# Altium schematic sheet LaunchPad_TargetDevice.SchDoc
size 431 x 279 mm; Date: Not shown in title block; ApprovedBy: Not shown in title block; CheckedBy: Not shown in title block; Author: Not shown in title block; CompanyName: Not shown in title block; Engineer: Not shown in title block; Organization: Not shown in title block; Address1: Not shown in title block; Address2: Not shown in title block; Address3: Not shown in title block; Address4: Not shown in title block; DocumentNumber: 2; Revision: Use project parameter SCH_Rev; SheetNumber: 2; SheetTotal: 3; PageSetup: Record=PageOptions¦CenterHorizontal=True¦CenterVertical=True¦PrintScale=1.00¦XCorrection=1.00¦YCorrection=1.00¦PrintKind=0¦BorderSize=5000000¦LeftOffset=0¦BottomOffset=0¦Orientation=2¦PaperLength=1000¦PaperWidth=1000¦Scale=100¦PaperSource=15¦PrintQuality=600¦MediaType=1¦DitherType=10¦PaperKind=Letter¦PrintScaleMode=1
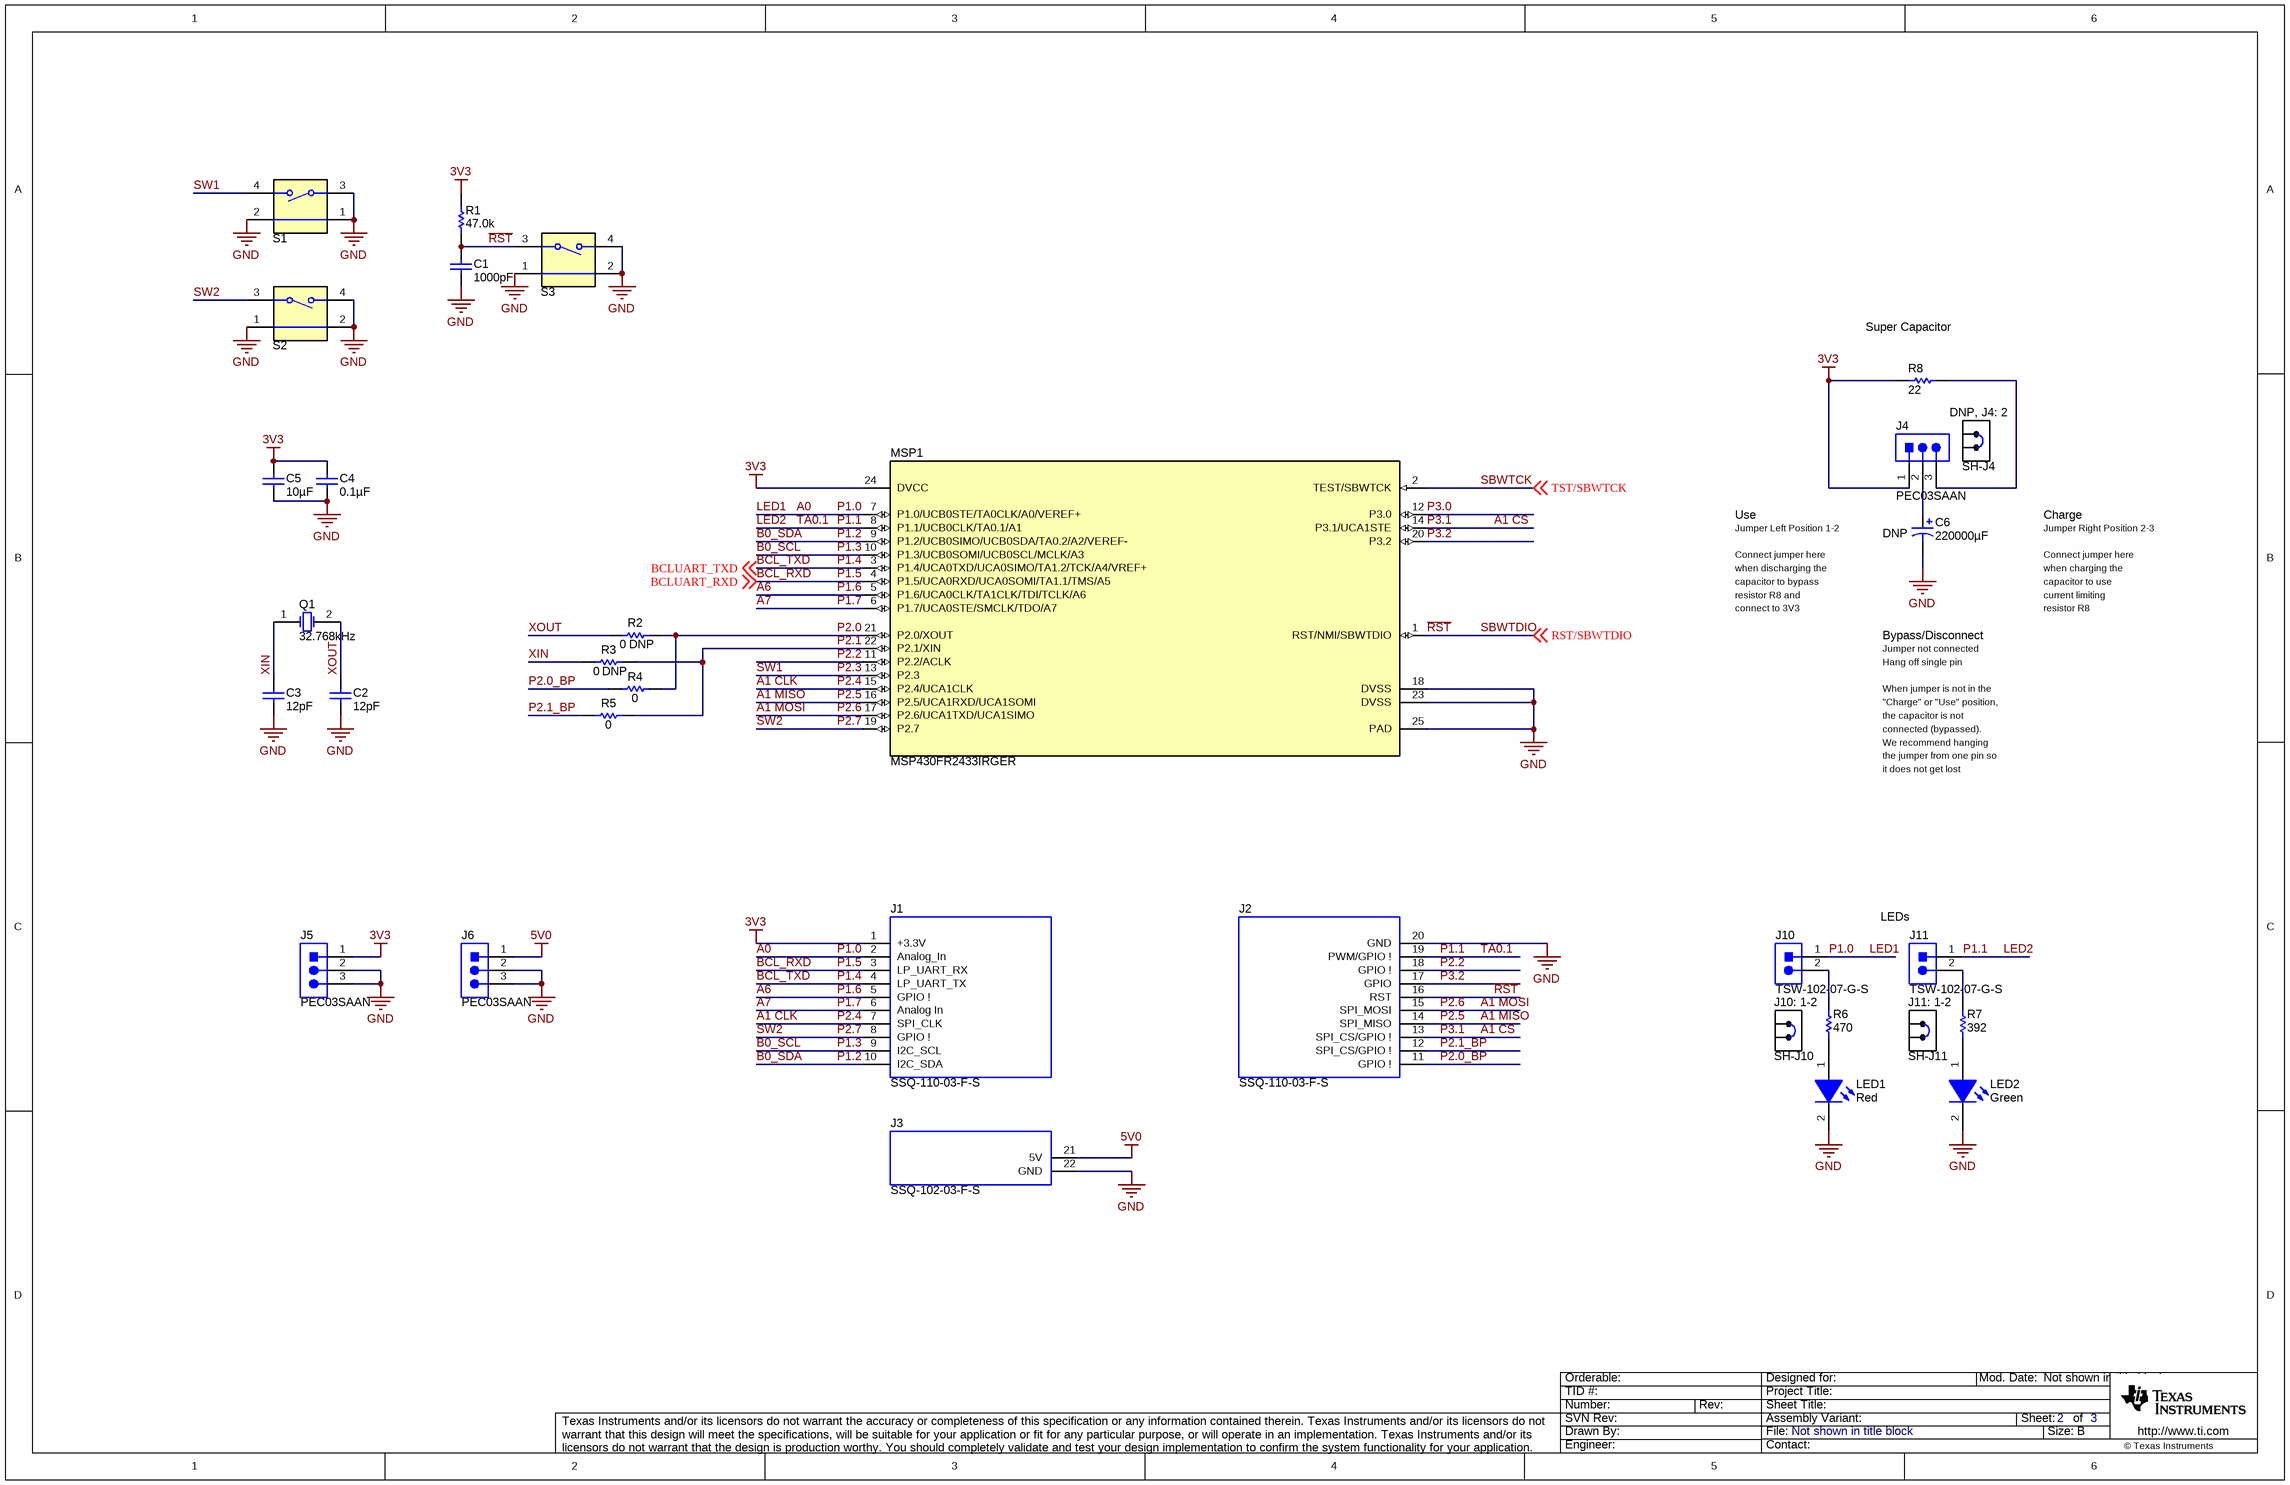
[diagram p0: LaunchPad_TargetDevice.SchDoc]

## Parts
C1  ValueDisplayed: 1000pF  [0402]  (hidden comment: GRM155R71H102KA01D)
C2  ValueDisplayed: 12pF  [0402]  (hidden comment: GRM1555C1E120JA01D)
C3  ValueDisplayed: 12pF  [0402]  (hidden comment: GRM1555C1E120JA01D)
C4  ValueDisplayed: 0.1µF  [0402]  (hidden comment: GRM155R61H104ME14D)
C5  ValueDisplayed: 10µF  [0603]  (hidden comment: GRM188R60J106ME84)
C6  ValueDisplayed: 220000µF  Note: DNP  [SD_1050x600]  (hidden comment: EEC-S0HD224H)
J1  SSQ-110-03-F-S  [BoosterPack_20pin_J1]
J2  SSQ-110-03-F-S  [BoosterPack_20pin_J2]
J3  SSQ-102-03-F-S  [BoosterPack_20pin_J3]
J4  PEC03SAAN  [CONN_PEC03SAAN]
J5  PEC03SAAN  [PEC03SAAN_Launchpad_3V3]
J6  PEC03SAAN  [PEC03SAAN_Launchpad_5V0]
J10  TSW-102-07-G-S  [TSW-102-07-G-S]
J11  TSW-102-07-G-S  [TSW-102-07-G-S]
LED1  value Red  [LED_LTST-C190_Red]  (hidden comment: LTST-C190CKT)
LED2  value Green  [LED_LTST-C190]  (hidden comment: LTST-C190GKT)
MSP1  MSP430FR2433IRGER  [RGE0024H]
Q1  Frequency: 32.768kHz  [Epson_FC-135]  (hidden comment: X1A0001410014)
R1  ValueDisplayed: 47.0k  [0402]  (hidden comment: RC0402FR-0747KL)
R2  ValueDisplayed: 0  Note: DNP  [0603]  (hidden comment: CRCW06030000Z0EA)
R3  ValueDisplayed: 0  Note: DNP  [0603]  (hidden comment: CRCW06030000Z0EA)
R4  ValueDisplayed: 0  [0603]  (hidden comment: CRCW06030000Z0EA)
R5  ValueDisplayed: 0  [0603]  (hidden comment: CRCW06030000Z0EA)
R6  ValueDisplayed: 470  [0402]  (hidden comment: RC0402FR-07470RL)
R7  ValueDisplayed: 392  [0402]  (hidden comment: CRCW0402392RFKED)
R8  ValueDisplayed: 22  [1206]  (hidden comment: CRCW120622R0JNEA)
S1  1188E-1K2-V-TR  [SW_1188E]  (value not drawn)
S2  1188E-1K2-V-TR  [SW_1188E]  (value not drawn)
S3  1188E-1K2-V-TR  [SW_1188E]  (value not drawn)
SH-J4  Note: DNP, J4: 2  [SNT-100-BK-G]  (hidden comment: SNT-100-BK-G)
SH-J10  Note: J10: 1-2  [SNT-100-BK-G]  (hidden comment: SNT-100-BK-G)
SH-J11  Note: J11: 1-2  [SNT-100-BK-G]  (hidden comment: SNT-100-BK-G)

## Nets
3V3: C4.1 C5.2 J1.1(+3.3V) J4.1 J5.1 MSP1.24(DVCC) R1.2 R8.1
5V0: J3.21(5V) J6.1
GND: C1.2 C2.2 C3.2 C4.2 C5.1 C6.2(-) J2.20(GND) J3.22(GND) J5.2 J5.3 J6.2 J6.3 LED1.2(K) LED2.2(K) MSP1.18(DVSS) MSP1.23(DVSS) MSP1.25(PAD) S1.1 S1.2 S1.3 S2.1 S2.2 S2.4 S3.1 S3.2 S3.4
A0: J1.2(Analog_In) J10.1 MSP1.7(P1.0/UCB0STE/TA0CLK/A0/VEREF+)  [also labelled LED1, P1.0]
A1 CLK: J1.7(SPI_CLK) MSP1.15(P2.4/UCA1CLK)  [also labelled P2.4]
A1 CS: J2.13(SPI_CS/GPIO_!) MSP1.14(P3.1/UCA1STE)  [also labelled P3.1]
A1 MISO: J2.14(SPI_MISO) MSP1.16(P2.5/UCA1RXD/UCA1SOMI)  [also labelled P2.5]
A1 MOSI: J2.15(SPI_MOSI) MSP1.17(P2.6/UCA1TXD/UCA1SIMO)  [also labelled P2.6]
A6: J1.5(GPIO_!) MSP1.5(P1.6/UCA0CLK/TA1CLK/TDI/TCLK/A6)  [also labelled P1.6]
A7: J1.6(Analog_In) MSP1.6(P1.7/UCA0STE/SMCLK/TDO/A7)  [also labelled P1.7]
B0_SCL: J1.9(I2C_SCL) MSP1.10(P1.3/UCB0SOMI/UCB0SCL/MCLK/A3)  [also labelled P1.3]
B0_SDA: J1.10(I2C_SDA) MSP1.9(P1.2/UCB0SIMO/UCB0SDA/TA0.2/A2/VEREF-)  [also labelled P1.2]
BCL_RXD: J1.3(LP_UART_RX) MSP1.4(P1.5/UCA0RXD/UCA0SOMI/TA1.1/TMS/A5) ; off-sheet BCLUART_RXD  [also labelled BCLUART_RXD, P1.5]
BCL_TXD: J1.4(LP_UART_TX) MSP1.3(P1.4/UCA0TXD/UCA0SIMO/TA1.2/TCK/A4/VREF+) ; off-sheet BCLUART_TXD  [also labelled BCLUART_TXD, P1.4]
LED2: J2.19(PWM/GPIO_!) J11.1 MSP1.8(P1.1/UCB0CLK/TA0.1/A1)  [also labelled P1.1, TA0.1]
P2.0: MSP1.21(P2.0/XOUT) R2.2 R4.2
P2.0_BP: J2.11(GPIO_!) R4.1
P2.1: MSP1.22(P2.1/XIN) R3.2 R5.2
P2.1_BP: J2.12(SPI_CS/GPIO_!) R5.1
P2.2: J2.18(GPIO_!) MSP1.11(P2.2/ACLK)
P2.3: MSP1.13(P2.3) S1.4  [also labelled SW1]
P2.7: J1.8(GPIO_!) MSP1.19(P2.7) S2.3  [also labelled SW2]
P3.0: MSP1.12(P3.0)
P3.2: J2.17(GPIO) MSP1.20(P3.2)
~{RST}: C1.1 J2.16(RST) MSP1.1(RST/NMI/SBWTDIO) R1.1 S3.3 ; off-sheet RST/SBWTDIO  [also labelled RST/SBWTDIO, SBWTDIO]
SBWTCK: MSP1.2(TEST/SBWTCK) ; off-sheet TST/SBWTCK  [also labelled TST/SBWTCK]
XIN: C3.1 Q1.1(OSC1) R3.1
XOUT: C2.1 Q1.2(OSC2) R2.1
NetC6_1: C6.1(+) J4.2
NetJ4_3: J4.3 R8.2
NetJ10_2: J10.2 R6.2
NetJ11_2: J11.2 R7.2
NetLED1_1: LED1.1(A) R6.1
NetLED2_1: LED2.1(A) R7.1

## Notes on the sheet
- (near R8) Super Capacitor
- Use
- Jumper Left Position 1-2
- Connect jumper here
- when discharging the
- Charge
- Jumper Right Position 2-3
- when charging the
- capacitor to bypass
- resistor R8 and
- connect to 3V3
- Bypass/Disconnect
- capacitor to use
- current limiting
- resistor R8
- Jumper not connected
- When jumper is not in the
- "Charge" or "Use" position,
- Hang off single pin
- the capacitor is not
- connected (bypassed).
- We recommend hanging
- the jumper from one pin so
- it does not get lost
- (near J11) LEDs

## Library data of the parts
C1 = GRM155R71H102KA01D: CAP, CERM, 1000 pF, 50 V, +/- 10%, X7R, 0402; Manufacturer: MuRata; Polarized: N; CompType: Capacitor; Value: 1000pF; U/M: EA; Cap_F: 0.000000001; Tolerance_%: 10; Value1: Unknown; VDC_V: 50; Value2: 50V; TaMin_C: -55; TaMax_C: 125; SizeArea_mm2: 0.5; SizeAreaWB_mm2: 3; SizeX_mm: 1; SizeZ_mm: 0.6; AEC Category: Q200
C2 C3 = GRM1555C1E120JA01D: CAP, CERM, 12 pF, 25 V, +/- 5%, C0G/NP0, 0402; Manufacturer: MuRata; Polarized: N; CompType: Capacitor; Value: 12pF; U/M: EA; Cap_F: 0.000000000012; Tolerance_%: 5; Value1: Unknown; VDC_V: 25; Value2: 25V; TaMin_C: -55; TaMax_C: 125; SizeArea_mm2: 0.5; SizeAreaWB_mm2: 3; SizeX_mm: 1; SizeZ_mm: 0.6; AEC Category: Q200
C4 = GRM155R61H104ME14D: CAP, CERM, 0.1 µF, 50 V, +/- 20%, X5R, 0402; Manufacturer: MuRata; Polarized: N; CompType: Capacitor; Value: 0.1uF; U/M: EA; Cap_F: 0.0000001; Tolerance_%: 20; Value1: Unknown; VDC_V: 50; Value2: 50V; TaMin_C: -55; TaMax_C: 85; SizeArea_mm2: 0.5; SizeAreaWB_mm2: 3; SizeX_mm: 1; SizeZ_mm: 0.6; AEC Category: Q200
C5 = GRM188R60J106ME84: CAP, CERM, 10 µF, 6.3 V, +/- 20%, X5R, 0603; Manufacturer: MuRata; Polarized: N; CompType: Capacitor; Value: 10uF; U/M: EA; Cap_F: 0.00001; Tolerance_%: 20; Value1: Unknown; VDC_V: 6.3; Value2: 6.3V; TaMin_C: -55; TaMax_C: 85; SizeArea_mm2: 1.28; SizeAreaWB_mm2: 4.68; SizeX_mm: 1.6; SizeY_mm: 0.8; SizeZ_mm: 1; AEC Category: Q200
C6 = EEC-S0HD224H: CAP, Electric Double Layer, 220000 µF, 5.5 V, +80/-20%, TH; Manufacturer: Panasonic; Polarized: Y; CompType: Capacitor; Value: 220000uF; U/M: EA; Cap_F: 0.22; Tolerance_%: 80; Value1: Unknown; VDC_V: 5.5; Value2: 5.5V; TaMin_C: -25; TaMax_C: 75; Cap_Case: 10.5x6mm; SizeAreaWB_mm2: 168.75; SizeArea_mm2: 120.75; SizeX_mm: 11.5; SizeY_mm: 10.5; SizeZ_mm: 6; AEC Category: Q200; AEC Qualified: N
J1 = BoosterPack_20pin_J1: Receptacle, 2.54mm, 10x1, Gold, TH; Manufacturer: Samtec; Alternate Manufacturer: Major League Electronics; Alternate PartNumber: SSHQ-110-S-08-G-LF; SymbolCreator: a0412235; Note: Booster Pack 20 pin J1
J2 = BoosterPack_20pin_J2: Receptacle, 2.54mm, 10x1, Gold, TH; Manufacturer: Samtec; Alternate Manufacturer: Major League Electronics; Alternate PartNumber: SSHQ-110-S-08-G-LF; SymbolCreator: a0412235; Note: Booster Pack 20 pin J2
J3 = BoosterPack_20pin_J3: Receptacle, 2.54mm, 2x1, Gold, TH; Manufacturer: Samtec; SymbolCreator: a0412235; Note: Booster Pack 20 pin J3
J4 = PEC03SAAN: Header, 100mil, 3x1, Tin, TH; Manufacturer: Sullins Connector Solutions; SymbolCreator: a0412235; Pitch_mm: 2.54; Gender: Male; Shrouded: N; Row_Count: 1; Current_A: 3; Voltage_V: 1800; Cert_UL: Y
J5 J6 = PEC03SAAN: Header, 100mil, 3x1, Tin, TH; Manufacturer: Sullins Connector Solutions; SymbolCreator: a0799628; Pitch_mm: 2.54; Gender: Male; Shrouded: N; Row_Count: 1; Current_A: 3; Voltage_V: 1800; Cert_UL: Y
J10 J11 = TSW-102-07-G-S: Header, 100mil, 2x1, Gold, TH; Manufacturer: Samtec; SymbolCreator: a0412235; Pitch_mm: 2.54; Gender: Male; Shrouded: N; Row_Count: 1; Current_A: 6.3; Voltage_V: 550; Cert_CSA: Y
LED1 = LTST-C190CKT: LED, Red, SMD; Manufacturer: Lite-On; Vf_V: 2; Value2: 2V; Io_A: 0.02; Tjmax_C: 85; Power_TotalModule: 0.0625; Value1: 0.0625W; U/M: EA
LED2 = LTST-C190GKT: LED, Green, SMD; Manufacturer: Lite-On; Vf_V: 2.1; Value2: 2.1V; Io_A: 0.02; Power_TotalModule: 0.1; Value1: 0.1W; U/M: EA
MSP1 = MSP430FR2433IRGER: MSP430FR2433 16 MHz Ultra-Low-Power Microcontroller with 16 KB FRAM, 4 KB RAM, 19 IO, 4 Timers, RGE0024H (VQFN-24); Alternate PartNumber: MSP430FR2433IRGET; Manufacturer: Texas Instruments; SymbolCreator: Altium; SizeArea_mm2: 16; SizeAreaWB_mm2: 25; SizeX_mm: 4; SizeZ_mm: 1; CompType: IC; U/M: EA; Note: TI Provided
Q1 = X1A0001410014: Crystal, 32.768 KHz, 12.5 pF, SMD; Manufacturer: Epson; SymbolCreator: a0412235; U/M: EA; TaMin_C: -40; TaMax_C: 85; Note: Use Exact Part, TI Provided
R1 = RC0402FR-0747KL: RES, 47.0 k, 1%, 0.0625 W, 0402; Manufacturer: Yageo America; CompType: Resistor; Value: 47.0k; Res_ohm: 47000; Value_Code: 47k0; Tolerance_%: 1; Power_W: 0.0625; VDC_V: 50; TempCo: 100 ppm/C; SizeArea_mm2: 0.5; SizeZ_mm: 0.6; U/M: EA; AEC Category: Q200; AEC Qualified: N
R2-R5 = CRCW06030000Z0EA: RES, 0, 5%, 0.1 W, 0603; Manufacturer: Vishay-Dale; CompType: Resistor; Value: 0; Value_Code: 0000; Tolerance_%: 5; Power_W: 0.1; Value2: 0.1W; VDC_V: 75; TempCo: 200 ppm/C; SizeArea_mm2: 1.28; SizeX_mm: 1.6; SizeY_mm: 0.8; SizeZ_mm: 1; EIA_Code: E24; U/M: EA; AEC Category: Q200
R6 = RC0402FR-07470RL: RES, 470, 1%, 0.063 W, 0402; Manufacturer: Yageo America; CompType: Resistor; Value: 470; Value_Code: 470R; Tolerance_%: 1; Power_W: 0.063; Value2: 0.063W; VDC_V: 50; TempCo: 100 ppm/C; SizeArea_mm2: 0.5; SizeZ_mm: 0.6; U/M: EA; AEC Category: Q200; AEC Qualified: N
R7 = CRCW0402392RFKED: RES, 392, 1%, 0.063 W, 0402; Manufacturer: Vishay-Dale; CompType: Resistor; Value: 392; Value_Code: 392R; Tolerance_%: 1; Power_W: 0.063; Value2: 0.063W; VDC_V: 50; TempCo: 100 ppm/C; SizeArea_mm2: 0.5; SizeZ_mm: 0.6; EIA_Code: E96; U/M: EA; AEC Category: Q200
R8 = CRCW120622R0JNEA: RES, 22, 5%, 0.25 W, 1206; Manufacturer: Vishay-Dale; CompType: Resistor; Value: 22; Value_Code: 22R0; Tolerance_%: 5; Power_W: 0.25; Value2: 0.25W; VDC_V: 200; TempCo: 200 ppm/C; SizeArea_mm2: 5.12; SizeX_mm: 3.2; SizeY_mm: 1.6; SizeZ_mm: 1.35; EIA_Code: E24; U/M: EA; AEC Category: Q200
S1-S3 = 1188E-1K2-V-TR: Switch, SPST, 0.05 A, 12 VDC, SMD; Manufacturer: Diptronics; SymbolCreator: Altium; SizeAreaWB_mm2: 53.9; SizeArea_mm2: 27.3; SizeX_mm: 7.8; SizeY_mm: 3.5; VDC_V: 12; PositionCount: 1; CurrentRating_mA: 50
SH-J4 SH-J10 SH-J11 = SNT-100-BK-G: Shunt, 100mil, Gold plated, Black; Manufacturer: Samtec; Alternate Manufacturer: 3M; Alternate PartNumber: 969102-0000-DA; Value: 1x2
